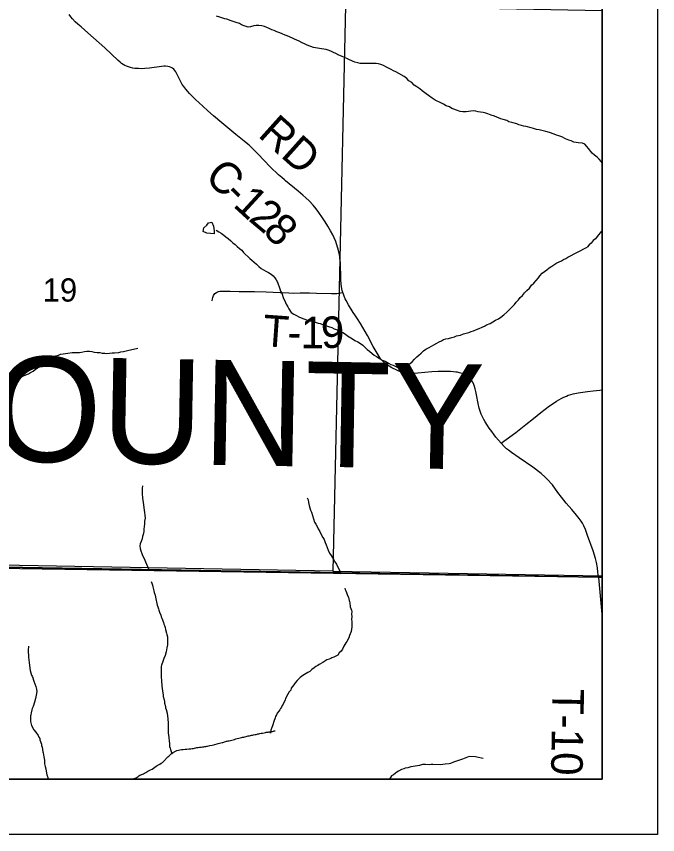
# Model space of a CAD drawing. Extents: x 0 to 34, y 0 to 22.
# Drawn here: x 29.261 to 30.417, y 14 to 15.474 of the extents above; entities that cross this region are included whole.
import ezdxf

# ---------------------------------------------------------------- set-up
doc = ezdxf.new("R2010")
doc.units = 0
for name, color, linetype in [('GM_X_Corporation', 7, 'Continuous'), ('GM_X_County', 7, 'Continuous'), ('GM_X_County_Road', 7, 'Continuous'), ('GM_X_County_Road_Text', 7, 'Continuous'), ('GM_X_County_Text', 7, 'Continuous'), ('GM_X_Minor_River', 7, 'Continuous'), ('GM_X_Section_Text', 7, 'Continuous'), ('GM_X_Township_Road', 7, 'Continuous'), ('GM_X_Township_Road_Text', 7, 'Continuous'), ('SH_Data', 7, 'Continuous')]:
    doc.layers.add(name, color=color, linetype=linetype)

msp = doc.modelspace()

# ---------------------------------------------------------------- linework, layer by layer
at = {"layer": 'GM_X_Corporation'}
for points in [[(27.8031, 14.5091), (28.4032, 14.497), (28.7853, 14.4893), (29.1713, 14.4832), (29.2367, 14.4822), (30.3098, 14.464), (30.3167, 14.4639), (30.3167, 20.9), (27.1022, 20.9)], [(27.8031, 14.5091), (28.4032, 14.497), (28.7853, 14.4893), (29.1713, 14.4832), (29.2367, 14.4822), (30.3098, 14.464), (30.3167, 14.4639), (30.3167, 20.3649), (29.5503, 20.3788), (27.6751, 20.4106)]]:
    msp.add_lwpolyline(points, dxfattribs=at)
for points in [[(28.8464, 15.5116), (29.8543, 15.4933), (29.8316, 14.4749), (28.8354, 14.4926)], [(30.3167, 14.4663), (30.3167, 15.4843), (29.8543, 15.4933), (29.8316, 14.4749)], [(23.5167, 14.5642), (23.5167, 14.1), (30.3167, 14.1), (30.3167, 14.4639), (30.3098, 14.464), (29.2367, 14.4822), (29.1713, 14.4832), (28.7853, 14.4893), (28.4032, 14.497), (27.8031, 14.5091), (27.2999, 14.5107), (27.0057, 14.5136), (26.7998, 14.5186), (26.3333, 14.5233), (26.009, 14.53), (25.56, 14.5392), (25.0494, 14.5496), (24.9788, 14.5503), (24.414, 14.5556), (24.4108, 14.5557), (23.7464, 14.562)], [(27.795, 14.1), (30.3167, 14.1), (30.3167, 14.4639), (30.3098, 14.464), (29.2367, 14.4822), (29.1713, 14.4832), (28.7853, 14.4893), (28.4032, 14.497), (27.8031, 14.5091)]]:
    msp.add_lwpolyline(points, close=True, dxfattribs=at)
at = {"layer": 'GM_X_County'}
msp.add_line((23.5167, 14.5642), (30.3167, 14.4639), dxfattribs=at)
at = {"layer": 'GM_X_County_Road'}
msp.add_lwpolyline([(30.31, 14.4635), (30.3092, 14.4732), (30.3083, 14.4809), (30.3066, 14.4904), (30.3046, 14.4978), (30.3005, 14.5114), (30.2906, 14.5391), (30.2869, 14.5498), (30.2838, 14.5562), (30.2812, 14.5612), (30.2787, 14.5651), (30.2756, 14.5696), (30.2703, 14.5759), (30.2619, 14.5858), (30.2521, 14.5973), (30.2435, 14.6078), (30.2366, 14.6165), (30.227, 14.6301), (30.2249, 14.6328), (30.2192, 14.639), (30.2142, 14.644), (30.2068, 14.6507), (30.192, 14.6622), (30.1671, 14.6791), (30.1536, 14.6885), (30.1481, 14.6925), (30.1447, 14.6951), (30.1406, 14.699), (30.1348, 14.7051), (30.1251, 14.7165), (30.1219, 14.7206), (30.1177, 14.7265), (30.113, 14.7327), (30.1101, 14.737), (30.1059, 14.7441), (30.1038, 14.7482), (30.1013, 14.753), (30.099, 14.7578), (30.097, 14.763), (30.0954, 14.7685), (30.0935, 14.7769), (30.0903, 14.7925), (30.0891, 14.7982), (30.088, 14.803), (30.0867, 14.8072), (30.0853, 14.8113), (30.0836, 14.8154), (30.0814, 14.8186), (30.0778, 14.8227), (30.0738, 14.8261), (30.0713, 14.8277), (30.0684, 14.829), (30.0643, 14.8308), (30.06, 14.8322), (30.0563, 14.8331), (30.053, 14.8336), (30.0492, 14.8341), (30.0437, 14.8343), (30.0323, 14.8346), (30.021, 14.8345), (30.0101, 14.8338), (29.9849, 14.8317), (29.9765, 14.8309), (29.97, 14.8306), (29.9612, 14.8312), (29.9579, 14.8319), (29.9558, 14.8325), (29.9379, 14.8411), (29.9329, 14.8442), (29.9283, 14.8472), (29.9255, 14.8493), (29.9221, 14.8524), (29.9175, 14.8576), (29.9149, 14.8613), (29.9112, 14.8673), (29.9042, 14.8797), (29.8938, 14.8993), (29.8812, 14.9208), (29.8757, 14.9296), (29.8734, 14.9331), (29.8711, 14.9364), (29.8679, 14.941), (29.8597, 14.9546), (29.8554, 14.9625), (29.854, 14.9655), (29.8519, 14.9704), (29.8506, 14.9737), (29.8495, 14.9771), (29.8486, 14.9802), (29.848, 14.9833), (29.8468, 14.992), (29.8462, 14.9995), (29.8458, 15.008), (29.8455, 15.023), (29.8451, 15.031), (29.8444, 15.038), (29.8439, 15.0418), (29.8423, 15.0499), (29.8407, 15.0566), (29.8382, 15.0646), (29.8367, 15.069), (29.8341, 15.0751), (29.8314, 15.0807), (29.8275, 15.0881), (29.8226, 15.0964), (29.8177, 15.1043), (29.8129, 15.1115), (29.8061, 15.1213), (29.8013, 15.1278), (29.7959, 15.1343), (29.7887, 15.1422), (29.7829, 15.1476), (29.7774, 15.1524), (29.7689, 15.1597), (29.7461, 15.1783), (29.7444, 15.1798), (29.7395, 15.1838), (29.7337, 15.189), (29.7186, 15.2032), (29.6968, 15.2261), (29.6863, 15.237), (29.6806, 15.2423), (29.6755, 15.2466), (29.6717, 15.2497), (29.6568, 15.2615), (29.6457, 15.2708), (29.6318, 15.2828), (29.6167, 15.2955), (29.6062, 15.3045), (29.5971, 15.3128), (29.5841, 15.3249), (29.5806, 15.3281), (29.5734, 15.3354), (29.5701, 15.3389), (29.5666, 15.343), (29.5629, 15.3478), (29.5604, 15.3516), (29.5583, 15.3554), (29.5485, 15.3744), (29.5468, 15.3772), (29.545, 15.3793), (29.5425, 15.3813), (29.5405, 15.3822), (29.5375, 15.3835), (29.5344, 15.3843), (29.5303, 15.3846), (29.5273, 15.3845), (29.5231, 15.3841), (29.5014, 15.3812), (29.4931, 15.3805), (29.486, 15.3802), (29.4812, 15.3803), (29.4751, 15.3806), (29.471, 15.3812), (29.4672, 15.3822), (29.4632, 15.3835), (29.4599, 15.3847), (29.4567, 15.3862), (29.4537, 15.3878), (29.4509, 15.3898), (29.4483, 15.3918), (29.445, 15.3947), (29.4209, 15.4176), (29.3903, 15.4447), (29.3779, 15.4555), (29.372, 15.4604), (29.3673, 15.4647), (29.3623, 15.4699), (29.3593, 15.4735), (29.3563, 15.4777)], dxfattribs=at)
at = {"layer": 'GM_X_Minor_River'}
for points in [[(29.8367, 15.4076), (29.8329, 15.4094), (29.8279, 15.4116), (29.8234, 15.4134), (29.8196, 15.4145), (29.8112, 15.4159), (29.804, 15.4169), (29.7968, 15.4186), (29.7854, 15.4226), (29.7804, 15.4248), (29.7762, 15.427), (29.7709, 15.4295), (29.7667, 15.4317), (29.7625, 15.4336), (29.7587, 15.435), (29.7495, 15.4394), (29.7457, 15.4408), (29.7404, 15.443), (29.7358, 15.4448), (29.7309, 15.4466), (29.7259, 15.4488), (29.7217, 15.4503), (29.7167, 15.4525), (29.7129, 15.4543), (29.7087, 15.4561), (29.7034, 15.4575), (29.6985, 15.4582), (29.6936, 15.4581), (29.6894, 15.4576), (29.683, 15.4556), (29.6789, 15.4552), (29.672, 15.4573), (29.6671, 15.4591), (29.6632, 15.4617), (29.6575, 15.4635), (29.6522, 15.4653), (29.6484, 15.4664), (29.6408, 15.4693), (29.637, 15.4703), (29.6317, 15.4718), (29.6278, 15.4732), (29.6218, 15.475)], [(30.3167, 15.2108), (30.3154, 15.2122), (30.3111, 15.2171), (30.3076, 15.2208), (30.303, 15.2242), (30.2988, 15.2279), (30.2919, 15.2361), (30.2891, 15.2402), (30.2853, 15.2443), (30.2811, 15.2458), (30.2735, 15.2464), (30.2697, 15.2471), (30.2656, 15.2478), (30.2606, 15.2499), (30.2568, 15.2514), (30.2507, 15.2539), (30.2438, 15.2572), (30.2389, 15.2594), (30.2347, 15.2605), (30.2305, 15.2619), (30.2221, 15.2652), (30.2153, 15.2669), (30.2107, 15.268), (30.2031, 15.2701), (30.1986, 15.2708), (30.1932, 15.2722), (30.1887, 15.2733), (30.1799, 15.2758), (30.1758, 15.2765), (30.1712, 15.2779), (30.1666, 15.279), (30.1628, 15.2808), (30.1541, 15.2833), (30.1487, 15.2847), (30.1449, 15.2869), (30.1381, 15.2887), (30.1339, 15.2901), (30.1267, 15.293), (30.1228, 15.2945), (30.1168, 15.2966), (30.111, 15.2988), (30.1069, 15.3003), (30.1023, 15.3013), (30.0974, 15.302), (30.0936, 15.3027), (30.089, 15.3037), (30.0845, 15.3044), (30.0716, 15.3027), (30.066, 15.3022), (30.061, 15.3029), (30.0542, 15.3054), (30.0496, 15.3072), (30.0458, 15.3086), (30.0416, 15.3112), (30.0355, 15.3134), (30.0309, 15.3163), (30.0259, 15.3185), (30.016, 15.3233), (30.0103, 15.3273), (30.0041, 15.3318), (29.9999, 15.3351), (29.9926, 15.3403), (29.9884, 15.3436), (29.9827, 15.3477), (29.9781, 15.3506), (29.9738, 15.3551), (29.9685, 15.3584), (29.965, 15.3625), (29.96, 15.3659), (29.9505, 15.3714), (29.9448, 15.3743), (29.9409, 15.3765), (29.9364, 15.3787), (29.9272, 15.3835), (29.923, 15.386), (29.918, 15.3878), (29.9139, 15.3889), (29.9097, 15.3896), (29.9036, 15.3895), (29.8987, 15.3898), (29.8847, 15.3895), (29.8805, 15.3898), (29.8764, 15.3905), (29.8714, 15.3919), (29.8615, 15.3963), (29.8577, 15.3981), (29.847, 15.4029), (29.8421, 15.4047), (29.8367, 15.4076)], [(29.6175, 15.089), (29.618, 15.0826), (29.6043, 15.0836), (29.5979, 15.0869), (29.5993, 15.0934), (29.6046, 15.0984), (29.6076, 15.1026), (29.6136, 15.1034), (29.6163, 15.0962), (29.6176, 15.0879)], [(29.6213, 15.0894), (29.6259, 15.0861), (29.6305, 15.0838), (29.635, 15.0804), (29.6389, 15.0771), (29.643, 15.0741), (29.6476, 15.0699), (29.6514, 15.0665), (29.6556, 15.0635), (29.6594, 15.0598), (29.6633, 15.0564), (29.6675, 15.053), (29.6709, 15.0492), (29.682, 15.0383), (29.6858, 15.035), (29.6896, 15.0316), (29.6942, 15.0282), (29.698, 15.0237), (29.7022, 15.0199), (29.7064, 15.0177), (29.7109, 15.0154), (29.7159, 15.0128), (29.7205, 15.0102), (29.7243, 15.0072), (29.7273, 15.0034), (29.7296, 14.9997), (29.7316, 14.9955), (29.7331, 14.9917), (29.7347, 14.9872), (29.7358, 14.9834), (29.7374, 14.9792), (29.7397, 14.9754), (29.7428, 14.9663), (29.7451, 14.9618), (29.7474, 14.9557), (29.7505, 14.9512), (29.7524, 14.9474), (29.7566, 14.941), (29.7612, 14.938), (29.7661, 14.9354), (29.7703, 14.9328), (29.7745, 14.9313), (29.784, 14.9276), (29.7897, 14.9261), (29.7943, 14.925), (29.7996, 14.9236), (29.8049, 14.9217), (29.8087, 14.921), (29.8163, 14.918), (29.8239, 14.9158), (29.8296, 14.914), (29.8338, 14.9117), (29.8391, 14.9099), (29.8448, 14.9069), (29.8493, 14.9047), (29.8543, 14.9017), (29.8581, 14.8987), (29.8672, 14.8934), (29.8714, 14.8904), (29.8764, 14.8878), (29.8813, 14.8848), (29.8855, 14.8818), (29.8931, 14.8743), (29.8973, 14.8709), (29.9023, 14.8672), (29.9061, 14.8642), (29.9103, 14.8615), (29.9149, 14.8585), (29.9206, 14.8552), (29.9259, 14.8529), (29.9316, 14.8496), (29.9358, 14.8473), (29.94, 14.8459), (29.9438, 14.844), (29.9476, 14.8425), (29.9529, 14.8418), (29.9567, 14.8422), (29.9612, 14.843), (29.9657, 14.8461), (29.971, 14.8488), (29.9747, 14.8519), (29.9785, 14.8565), (29.9826, 14.8607), (29.9864, 14.8642), (29.9909, 14.8676), (29.995, 14.8715), (29.9992, 14.8749), (30.0052, 14.8776), (30.0093, 14.8799), (30.0135, 14.8826), (30.0191, 14.8857), (30.0229, 14.8881), (30.0274, 14.89), (30.0312, 14.8919), (30.0354, 14.8931), (30.0399, 14.8939), (30.0459, 14.8955), (30.0509, 14.8971), (30.0546, 14.8986), (30.0614, 14.9002), (30.0667, 14.9021)], [(30.3167, 15.0892), (30.3153, 15.0872), (30.3079, 15.0779), (30.3045, 15.0737), (30.3008, 15.0706), (30.2971, 15.066), (30.2934, 15.0625), (30.2896, 15.0586)], [(30.0667, 14.9021), (30.0765, 14.9049), (30.0807, 14.9068), (30.0852, 14.908), (30.0905, 14.91), (30.095, 14.9123), (30.1003, 14.9142), (30.1048, 14.9162), (30.1086, 14.9185), (30.115, 14.9212), (30.1199, 14.9239), (30.1248, 14.927), (30.1297, 14.9293), (30.1339, 14.9324), (30.1395, 14.9366), (30.1448, 14.9416), (30.1504, 14.9466), (30.1538, 14.9505), (30.159, 14.9554), (30.162, 14.9596), (30.1658, 14.9635), (30.1688, 14.9677), (30.1733, 14.9715), (30.1767, 14.9761), (30.1812, 14.9807), (30.1857, 14.9849), (30.1894, 14.9899), (30.1939, 14.9934), (30.1977, 14.9987), (30.2018, 15.0033), (30.2044, 15.0072), (30.2089, 15.0118), (30.2127, 15.0148), (30.2172, 15.0179), (30.2213, 15.0214), (30.2259, 15.0245), (30.2296, 15.0268), (30.2349, 15.0302), (30.2394, 15.0322), (30.2432, 15.0341), (30.247, 15.0364), (30.2511, 15.0384), (30.2549, 15.0403), (30.2896, 15.0586)], [(29.2575, 14.8196), (29.262, 14.8208), (29.2658, 14.8224), (29.2741, 14.8266), (29.2786, 14.8286), (29.2831, 14.8301), (29.2869, 14.8325), (29.2914, 14.8352), (29.2955, 14.8379), (29.2997, 14.8413), (29.3034, 14.844), (29.3072, 14.8475), (29.311, 14.8505), (29.3151, 14.8536), (29.32, 14.8563), (29.3328, 14.8629), (29.3374, 14.8641), (29.3411, 14.8656), (29.3457, 14.8664), (29.3498, 14.8672), (29.3544, 14.8677), (29.3619, 14.8685), (29.3706, 14.8686), (29.3752, 14.869), (29.379, 14.8694), (29.3839, 14.8706), (29.3884, 14.871), (29.3933, 14.8711), (29.3971, 14.8707), (29.4013, 14.8696), (29.407, 14.8689), (29.4115, 14.8686), (29.4161, 14.8675), (29.4206, 14.8675), (29.4244, 14.8672), (29.4339, 14.868), (29.4384, 14.8681), (29.446, 14.8689), (29.4498, 14.8697), (29.4543, 14.8705), (29.4619, 14.8721), (29.48, 14.8768)], [(29.4885, 14.6288), (29.4878, 14.6235), (29.4879, 14.6147), (29.4887, 14.606), (29.4896, 14.5984), (29.4904, 14.5942), (29.4912, 14.5889), (29.4916, 14.5844), (29.4924, 14.5802), (29.4928, 14.5756), (29.4932, 14.5703), (29.4925, 14.565), (29.4922, 14.5593), (29.4918, 14.5555), (29.4911, 14.5505), (29.4908, 14.546), (29.49, 14.541), (29.4889, 14.5372), (29.4882, 14.533), (29.486, 14.5281), (29.4845, 14.5239), (29.4838, 14.5201), (29.4842, 14.5155), (29.4854, 14.5113), (29.4873, 14.5068), (29.4889, 14.503), (29.4908, 14.4985), (29.5008, 14.4762)], [(29.7852, 14.6069), (29.7868, 14.6031), (29.7879, 14.5986), (29.7891, 14.5929), (29.7903, 14.5891), (29.7915, 14.5849), (29.7934, 14.5808), (29.7988, 14.5633), (29.8012, 14.5596), (29.8031, 14.5554), (29.805, 14.5509), (29.8081, 14.5463), (29.8108, 14.5407), (29.8138, 14.5357), (29.8158, 14.5316), (29.8177, 14.5267), (29.8193, 14.5221), (29.8212, 14.5172), (29.8231, 14.5127), (29.8258, 14.5074), (29.8285, 14.5028), (29.8331, 14.4953), (29.835, 14.4915), (29.8381, 14.4873), (29.8465, 14.47)], [(29.5042, 14.4563), (29.5057, 14.4532), (29.5068, 14.4494), (29.5072, 14.4464), (29.509, 14.4395), (29.5097, 14.4361), (29.5116, 14.4312), (29.5127, 14.4251), (29.5146, 14.4163), (29.5153, 14.4133), (29.5164, 14.4102), (29.5175, 14.4068), (29.5179, 14.4042), (29.5194, 14.4007), (29.5216, 14.3954), (29.522, 14.3924), (29.5235, 14.3901), (29.5265, 14.3821), (29.5268, 14.3794), (29.528, 14.3771), (29.5294, 14.3733), (29.5298, 14.3699), (29.5317, 14.3631), (29.5324, 14.3608), (29.5335, 14.3562), (29.5334, 14.3422), (29.5326, 14.3368), (29.5314, 14.3296), (29.5295, 14.3228), (29.5272, 14.3175), (29.5253, 14.3122), (29.5229, 14.3054), (29.5225, 14.3027), (29.5225, 14.2997), (29.5221, 14.2959), (29.5221, 14.2921), (29.5224, 14.2883), (29.5224, 14.2826), (29.5228, 14.2792), (29.5227, 14.2754), (29.5235, 14.2701), (29.5235, 14.2678), (29.5242, 14.2632), (29.5249, 14.2594), (29.5253, 14.2552), (29.526, 14.2522), (29.526, 14.2492), (29.5278, 14.2427), (29.5282, 14.2396), (29.5282, 14.237), (29.53, 14.2309), (29.53, 14.2282), (29.5311, 14.2256), (29.533, 14.2191), (29.5341, 14.2088), (29.5344, 14.2062), (29.5348, 14.2035), (29.5351, 14.1956), (29.535, 14.183), (29.5354, 14.18), (29.5361, 14.1747), (29.5365, 14.1682), (29.5372, 14.164), (29.5372, 14.1614), (29.5375, 14.1591), (29.5383, 14.156), (29.539, 14.1534), (29.5416, 14.1463)], [(29.8532, 14.4442), (29.854, 14.4419), (29.8551, 14.4396), (29.8562, 14.4366), (29.8573, 14.4328), (29.8599, 14.4275), (29.8603, 14.4248), (29.861, 14.4221), (29.8614, 14.4198), (29.8621, 14.4176), (29.8629, 14.4103), (29.8651, 14.4046), (29.8658, 14.402), (29.8654, 14.3974), (29.8658, 14.3929), (29.8654, 14.3879), (29.8657, 14.3841), (29.8657, 14.3746), (29.8653, 14.3705), (29.8645, 14.3659), (29.8614, 14.3587), (29.8602, 14.3549), (29.8568, 14.3481), (29.8552, 14.3458), (29.8514, 14.3398), (29.8491, 14.3341), (29.8464, 14.3307), (29.843, 14.3273), (29.8407, 14.3235), (29.8331, 14.3198), (29.83, 14.3186), (29.8277, 14.3175), (29.8247, 14.3164), (29.8209, 14.3149), (29.8174, 14.3126), (29.8133, 14.3104), (29.8068, 14.3063), (29.8045, 14.3048), (29.8011, 14.3029), (29.798, 14.3006), (29.7938, 14.2976), (29.79, 14.2938), (29.7862, 14.2923), (29.7774, 14.2867), (29.7725, 14.2833), (29.7675, 14.278), (29.7637, 14.2735), (29.7614, 14.2701), (29.7564, 14.264), (29.7556, 14.2606), (29.7526, 14.2572), (29.7503, 14.2531), (29.7464, 14.2455), (29.7457, 14.2432), (29.7418, 14.2353), (29.7403, 14.2326), (29.7391, 14.2296), (29.7372, 14.2273), (29.7361, 14.2247), (29.7345, 14.2224), (29.7315, 14.2186), (29.7299, 14.2156), (29.7284, 14.2129), (29.7276, 14.2107), (29.7272, 14.2084), (29.7257, 14.2054), (29.7226, 14.1963), (29.7214, 14.1929), (29.7199, 14.1883), (29.7191, 14.183), (29.7178, 14.1852)], [(29.2833, 14.3399), (29.2829, 14.3323), (29.2832, 14.3198), (29.2843, 14.3103), (29.285, 14.305), (29.2865, 14.2955), (29.2887, 14.2875), (29.2906, 14.2841), (29.2928, 14.2765), (29.2962, 14.2669), (29.2976, 14.262), (29.298, 14.2578), (29.2972, 14.2514), (29.296, 14.2453), (29.2941, 14.2389), (29.2914, 14.2309), (29.2898, 14.2275), (29.2894, 14.2248), (29.2883, 14.2195), (29.2875, 14.2161), (29.2871, 14.2138), (29.2867, 14.21), (29.2867, 14.2066), (29.287, 14.2036), (29.2885, 14.1964), (29.2926, 14.1891), (29.2964, 14.1845), (29.3005, 14.1788), (29.3016, 14.1754), (29.3035, 14.1731), (29.3039, 14.1708), (29.3065, 14.1628), (29.3068, 14.1605), (29.3076, 14.1575), (29.309, 14.1495), (29.3098, 14.1472), (29.3109, 14.1404), (29.312, 14.1339), (29.3123, 14.1275), (29.3134, 14.1225), (29.3145, 14.1183), (29.316, 14.1107), (29.3164, 14.1077), (29.3182, 14.1031), (29.3185, 14.1)], [(30.1024, 14.1369), (30.0911, 14.1393), (30.0884, 14.14), (30.077, 14.1405), (30.0713, 14.1382), (30.0649, 14.136), (30.0546, 14.1323), (30.0489, 14.1304), (30.0436, 14.1282), (30.0413, 14.1274), (30.0337, 14.1271), (30.0299, 14.1263), (30.0261, 14.126), (30.0117, 14.1261), (30.0086, 14.1261), (30.0056, 14.1257), (29.9984, 14.1262), (29.9931, 14.1262), (29.9877, 14.1247), (29.976, 14.1229), (29.9722, 14.1222), (29.9665, 14.1203), (29.9619, 14.1199), (29.9596, 14.1188), (29.9551, 14.1173), (29.9501, 14.1143), (29.9471, 14.1128), (29.9406, 14.1079), (29.9375, 14.1057), (29.9334, 14.1)]]:
    msp.add_lwpolyline(points, dxfattribs=at)
msp.add_spline([(29.4905, 14.1097), (29.4984, 14.1143), (29.5033, 14.1166), (29.5131, 14.1232), (29.5222, 14.1285), (29.5267, 14.132), (29.5309, 14.1366), (29.5358, 14.1412), (29.5403, 14.1454), (29.546, 14.1492), (29.5505, 14.1515), (29.5619, 14.1535), (29.5755, 14.1547), (29.5805, 14.1555), (29.5888, 14.1571), (29.5994, 14.1583), (29.6059, 14.1595), (29.6229, 14.1634), (29.632, 14.1658), (29.6381, 14.1677), (29.6445, 14.1693), (29.6544, 14.1716), (29.6646, 14.1747), (29.6733, 14.1763), (29.6812, 14.1783), (29.6888, 14.1798), (29.6934, 14.1806), (29.6998, 14.1822), (29.7051, 14.183), (29.71, 14.1841), (29.7165, 14.185), (29.7214, 14.1857), (29.7275, 14.1873)], degree=3, dxfattribs=at)
msp.add_open_spline([(29.471, 14.1), (29.4725, 14.1006), (29.474, 14.101), (29.4753, 14.1016), (29.479, 14.1035), (29.4822, 14.1062), (29.4859, 14.1078), (29.4874, 14.1084), (29.489, 14.1091), (29.4905, 14.1097)], degree=3, dxfattribs=at)
at = {"layer": 'GM_X_Township_Road'}
for points in [[(29.6141, 14.9621), (29.6146, 14.9652), (29.6155, 14.9681), (29.6167, 14.9713), (29.6191, 14.9749), (29.6218, 14.977), (29.6236, 14.978), (29.6255, 14.9786), (29.6279, 14.9791), (29.6321, 14.9793), (29.6468, 14.9791), (29.663, 14.9786), (29.6904, 14.9784), (29.7115, 14.9781), (29.7365, 14.9768), (29.7522, 14.9761), (29.7601, 14.9759), (29.7728, 14.9761), (29.7896, 14.9762), (29.8024, 14.9758), (29.8289, 14.975), (29.8386, 14.9751), (29.8419, 14.9754), (29.8452, 14.976), (29.8495, 14.9771)], [(30.1348, 14.7051), (30.1398, 14.709), (30.1438, 14.7121), (30.1613, 14.7248), (30.1793, 14.739), (30.1929, 14.7497), (30.2065, 14.7606), (30.2216, 14.7725), (30.2284, 14.7771), (30.2342, 14.7808), (30.2431, 14.7858), (30.2479, 14.7883), (30.2522, 14.7902), (30.2556, 14.7916), (30.2602, 14.793), (30.2648, 14.7942), (30.2736, 14.7958), (30.2902, 14.7983), (30.3003, 14.7996), (30.3127, 14.8008), (30.3167, 14.8012)], [(30.31, 14.4635), (30.3162, 14.3975), (30.3167, 14.3959)]]:
    msp.add_lwpolyline(points, dxfattribs=at)
at = {"layer": 'SH_Data'}
for points in [[(23.4167, 21), (30.4167, 21), (30.4167, 14), (23.4167, 14)], [(23.5167, 20.9), (30.3167, 20.9), (30.3167, 14.1), (23.5167, 14.1)]]:
    msp.add_lwpolyline(points, close=True, dxfattribs=at)

# ---------------------------------------------------------------- texts
at = {"layer": 'GM_X_County_Road_Text'}
for s, height, rotation, p in [('RD', 0.05682, 318.1239, (29.6948, 15.2592)), ('C', 0.0568, 315.9605, (29.5984, 15.1829)), ('-', 0.0568, 316.2957, (29.6322, 15.1502)), ('1', 0.0568, 317.4863, (29.65, 15.1332)), ('2', 0.0568, 319.9614, (29.6778, 15.1077)), ('8', 0.0568, 313.9181, (29.7034, 15.0863))]:
    msp.add_text(s, height=height, rotation=rotation, dxfattribs=at).set_placement(p)
at = {"layer": 'GM_X_County_Text'}
msp.add_text('BELMONT COUNTY', height=0.189394, rotation=358.998, dxfattribs=at).set_placement((27.7391, 14.6991))
at = {"layer": 'GM_X_Section_Text'}
msp.add_text('19', height=0.04186, rotation=0, dxfattribs=at).set_placement((29.3087, 14.9605))
at = {"layer": 'GM_X_Township_Road_Text'}
for s, height, rotation, p in [('T', 0.0568, 355.893, (29.7039, 14.8805)), ('1', 0.0568, 359.404, (29.7734, 14.8766)), ('9', 0.0568, 1.8347, (29.811, 14.8763)), ('-', 0.0568, 358.3236, (29.7489, 14.8773)), ('T-10', 0.05682, 268.9688, (30.2274, 14.2632))]:
    msp.add_text(s, height=height, rotation=rotation, dxfattribs=at).set_placement(p)

doc.saveas('drawing.dxf')
